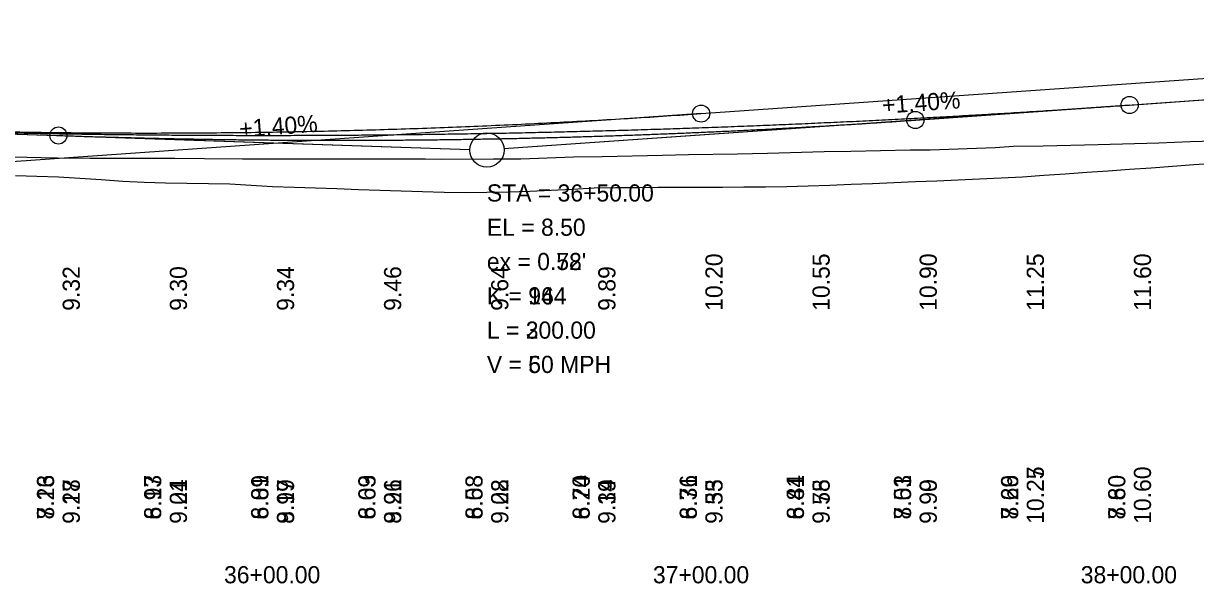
# Model space of a CAD drawing. Extents: x 3880794 to 3915434, y 287517 to 300173.
# Drawn here: x 3884080.1 to 3884353.7, y 296469.1 to 296599.8 of the extents above; entities that cross this region are included whole.
import ezdxf

# ---------------------------------------------------------------- set-up
doc = ezdxf.new("R2010")
doc.units = 0
for name, color, linetype in [('Level 1', 7, 'Continuous'), ('Level 2', 7, 'Continuous'), ('Level 30', 7, 'Continuous'), ('Level 31', 7, 'Continuous'), ('Level 32', 7, 'Continuous')]:
    doc.layers.add(name, color=color, linetype=linetype)

msp = doc.modelspace()

# ---------------------------------------------------------------- linework, layer by layer
at = {"layer": 'Level 1'}
for p, q in [((3884238.3, 296578.77), (3884538.3, 296599.8)), ((3884288.3, 296577.26), (3884538.3, 296594.76)), ((3884238.3, 296578.77), (3884042.29, 296565.04)), ((3884288.3, 296577.26), (3884192.29, 296570.54)), ((3884038.3, 296575.36), (3884088.3, 296573.66)), ((3884088.3, 296573.66), (3884184.3, 296570.39))]:
    msp.add_line(p, q, dxfattribs=at)
msp.add_lwpolyline([(3884067.5, 296568.95), (3884084.25, 296568.51), (3884088.11, 296568.41), (3884095.69, 296568.39), (3884105.7, 296568.38), (3884115.48, 296568.38), (3884122.37, 296568.31), (3884131.29, 296568.25), (3884136.3, 296568.22), (3884146.02, 296568.2), (3884152.71, 296568.19), (3884164.32, 296568.19), (3884173.94, 296568.18), (3884177.81, 296568.11), (3884189.81, 296568.18), (3884196.23, 296568.24), (3884208.54, 296568.65), (3884215.17, 296568.79), (3884229.31, 296569.1), (3884235.38, 296569.26), (3884246.77, 296569.4), (3884253.82, 296569.5), (3884267, 296569.89), (3884273.23, 296569.97), (3884287.11, 296570.3), (3884291.73, 296570.35), (3884306.93, 296570.86), (3884311.21, 296571.2), (3884318.13, 296571.24), (3884331, 296571.56), (3884345.09, 296571.95), (3884352.46, 296572.25), (3884366.62, 296572.68)], dxfattribs=at)
msp.add_circle((3884188.3, 296570.26), 4, dxfattribs=at)
for points in [[(3883838.3, 296594.09), (3883846.3, 296592.93), (3883854.3, 296591.81), (3883862.3, 296590.73), (3883870.3, 296589.67), (3883878.3, 296588.66), (3883886.3, 296587.67), (3883894.3, 296586.73), (3883902.3, 296585.81), (3883910.3, 296584.93), (3883918.3, 296584.09), (3883926.3, 296583.28), (3883934.3, 296582.51), (3883942.3, 296581.77), (3883950.3, 296581.06), (3883958.3, 296580.39), (3883966.3, 296579.76), (3883974.3, 296579.15), (3883982.3, 296578.59), (3883990.3, 296578.06), (3883998.3, 296577.56), (3884006.3, 296577.1), (3884014.3, 296576.67), (3884022.3, 296576.28), (3884030.3, 296575.92), (3884038.3, 296575.59), (3884046.3, 296575.31), (3884054.3, 296575.05), (3884062.3, 296574.83), (3884070.3, 296574.65), (3884078.3, 296574.5), (3884086.3, 296574.38), (3884094.3, 296574.3), (3884102.3, 296574.25), (3884110.3, 296574.24), (3884118.3, 296574.26), (3884126.3, 296574.32), (3884134.3, 296574.41), (3884142.3, 296574.54), (3884150.3, 296574.7), (3884158.3, 296574.9), (3884166.3, 296575.13), (3884174.3, 296575.4), (3884182.3, 296575.7), (3884190.3, 296576.03), (3884198.3, 296576.4), (3884206.3, 296576.81), (3884214.3, 296577.25), (3884222.3, 296577.72), (3884230.3, 296578.23), (3884238.3, 296578.77)], [(3884088.3, 296573.66), (3884092.3, 296573.53), (3884096.3, 296573.4), (3884100.3, 296573.29), (3884104.3, 296573.18), (3884108.3, 296573.08), (3884112.3, 296572.99), (3884116.3, 296572.91), (3884120.3, 296572.84), (3884124.3, 296572.77), (3884128.3, 296572.71), (3884132.3, 296572.66), (3884136.3, 296572.62), (3884140.3, 296572.59), (3884144.3, 296572.57), (3884148.3, 296572.55), (3884152.3, 296572.55), (3884156.3, 296572.55), (3884160.3, 296572.56), (3884164.3, 296572.57), (3884168.3, 296572.6), (3884172.3, 296572.64), (3884176.3, 296572.68), (3884180.3, 296572.73), (3884184.3, 296572.79), (3884188.3, 296572.86), (3884192.3, 296572.93), (3884196.3, 296573.02), (3884200.3, 296573.11), (3884204.3, 296573.21), (3884208.3, 296573.32), (3884212.3, 296573.44), (3884216.3, 296573.56), (3884220.3, 296573.7), (3884224.3, 296573.84), (3884228.3, 296573.99), (3884232.3, 296574.15), (3884236.3, 296574.32), (3884240.3, 296574.5), (3884244.3, 296574.68), (3884248.3, 296574.87), (3884252.3, 296575.07), (3884256.3, 296575.28), (3884260.3, 296575.5), (3884264.3, 296575.73), (3884268.3, 296575.96), (3884272.3, 296576.2), (3884276.3, 296576.45), (3884280.3, 296576.71), (3884284.3, 296576.98), (3884288.3, 296577.26)]]:
    msp.add_spline(points, degree=3, dxfattribs=at)
at = {"layer": 'Level 2'}
for p, q in [((3884338.3, 296580.76), (3884538.3, 296594.76)), ((3884338.3, 296580.76), (3884192.29, 296570.54)), ((3884038.3, 296575.36), (3884184.3, 296570.39))]:
    msp.add_line(p, q, dxfattribs=at)
msp.add_lwpolyline([(3884078.3, 296564.35), (3884083.3, 296564.19), (3884088.3, 296564.04), (3884093.3, 296563.74), (3884098.3, 296563.37), (3884103.3, 296562.98), (3884108.3, 296562.79), (3884113.3, 296562.61), (3884118.3, 296562.52), (3884123.3, 296562.46), (3884128.3, 296562.4), (3884133.3, 296562.1), (3884138.3, 296561.79), (3884143.3, 296561.58), (3884148.3, 296561.43), (3884153.3, 296561.27), (3884158.3, 296561.09), (3884163.3, 296560.91), (3884168.3, 296560.72), (3884173.3, 296560.56), (3884178.3, 296560.42), (3884183.3, 296560.37), (3884188.3, 296560.41), (3884193.3, 296560.53), (3884198.3, 296560.64), (3884203.3, 296560.88), (3884208.3, 296561.17), (3884213.3, 296561.45), (3884218.3, 296561.51), (3884223.3, 296561.54), (3884228.3, 296561.58), (3884233.3, 296561.58), (3884238.3, 296561.58), (3884243.3, 296561.6), (3884248.3, 296561.65), (3884253.3, 296561.69), (3884258.3, 296561.79), (3884263.3, 296561.95), (3884268.3, 296562.11), (3884273.3, 296562.29), (3884278.3, 296562.49), (3884283.3, 296562.69), (3884288.3, 296562.9), (3884293.3, 296563.12), (3884298.3, 296563.34), (3884303.3, 296563.58), (3884308.3, 296563.82), (3884313.3, 296564.05), (3884318.3, 296564.38), (3884323.3, 296564.74), (3884328.3, 296565.1), (3884333.3, 296565.44), (3884338.3, 296565.78), (3884343.3, 296566.13), (3884348.3, 296566.5), (3884353.3, 296566.87), (3884358.3, 296567.23)], dxfattribs=at)
for centre, radius in [((3884338.3, 296580.76), 2), ((3884188.3, 296570.26), 4)]:
    msp.add_circle(centre, radius, dxfattribs=at)
msp.add_spline([(3884038.3, 296575.36), (3884044.3, 296575.16), (3884050.3, 296574.97), (3884056.3, 296574.8), (3884062.3, 296574.64), (3884068.3, 296574.49), (3884074.3, 296574.36), (3884080.3, 296574.23), (3884086.3, 296574.12), (3884092.3, 296574.03), (3884098.3, 296573.94), (3884104.3, 296573.87), (3884110.3, 296573.81), (3884116.3, 296573.76), (3884122.3, 296573.72), (3884128.3, 296573.7), (3884134.3, 296573.69), (3884140.3, 296573.69), (3884146.3, 296573.71), (3884152.3, 296573.73), (3884158.3, 296573.77), (3884164.3, 296573.82), (3884170.3, 296573.89), (3884176.3, 296573.97), (3884182.3, 296574.06), (3884188.3, 296574.16), (3884194.3, 296574.27), (3884200.3, 296574.4), (3884206.3, 296574.54), (3884212.3, 296574.69), (3884218.3, 296574.85), (3884224.3, 296575.03), (3884230.3, 296575.22), (3884236.3, 296575.42), (3884242.3, 296575.63), (3884248.3, 296575.86), (3884254.3, 296576.1), (3884260.3, 296576.35), (3884266.3, 296576.62), (3884272.3, 296576.89), (3884278.3, 296577.18), (3884284.3, 296577.48), (3884290.3, 296577.8), (3884296.3, 296578.12), (3884302.3, 296578.46), (3884308.3, 296578.81), (3884314.3, 296579.18), (3884320.3, 296579.55), (3884326.3, 296579.94), (3884332.3, 296580.34), (3884338.3, 296580.76)], degree=3, dxfattribs=at)
at = {"layer": 'Level 31'}
for centre in [(3884238.3, 296578.77), (3884288.3, 296577.26), (3884088.3, 296573.66)]:
    msp.add_circle(centre, 2, dxfattribs=at)

# ---------------------------------------------------------------- texts
at = {"layer": 'Level 2'}
for s, rotation, p in [('+1.40%', 4.0042, (3884280.66, 296578.73)), ('10.27', 90, (3884318.3, 296483.07)), ('10.60', 90, (3884343.3, 296483.07)), ('9.27', 90, (3884093.3, 296483.07)), ('9.21', 90, (3884118.3, 296483.07)), ('9.19', 90, (3884143.3, 296483.07)), ('9.21', 90, (3884168.3, 296483.07)), ('9.28', 90, (3884193.3, 296483.07)), ('9.39', 90, (3884218.3, 296483.07)), ('9.55', 90, (3884243.3, 296483.07)), ('9.75', 90, (3884268.3, 296483.07)), ('9.99', 90, (3884293.3, 296483.07))]:
    msp.add_text(s, height=4, rotation=rotation, dxfattribs=at).set_placement(p)
for s, p in [('STA = 36+50.00', (3884188.3, 296558.26)), ('EL = 8.50', (3884188.3, 296550.26)), ("ex = 0.78'", (3884188.3, 296542.26)), ('K = 144', (3884188.3, 296534.26)), ('L = 300.00', (3884188.3, 296526.26)), ('V = 60 MPH', (3884188.3, 296518.26)), ('36+00.00', (3884126.96, 296469.2)), ('37+00.00', (3884227.05, 296469.2)), ('38+00.00', (3884326.9, 296469.2))]:
    msp.add_text(s, height=4, dxfattribs=at).set_placement(p)
at = {"layer": 'Level 30'}
for s, p in [('8.13', (3884087.3, 296484.08)), ('8.13', (3884112.3, 296484.08)), ('8.09', (3884137.3, 296484.08)), ('8.09', (3884162.3, 296484.08)), ('8.08', (3884187.3, 296484.08)), ('8.20', (3884212.3, 296484.08)), ('8.31', (3884237.3, 296484.08)), ('8.41', (3884262.3, 296484.08)), ('8.51', (3884287.3, 296484.08)), ('8.69', (3884312.3, 296484.08)), ('8.80', (3884337.3, 296484.08))]:
    msp.add_text(s, height=4, rotation=90, dxfattribs=at).set_placement(p)
for s, p in [('36+00.00', (3884126.96, 296469.2)), ('37+00.00', (3884227.05, 296469.2)), ('38+00.00', (3884326.9, 296469.2))]:
    msp.add_text(s, height=4, dxfattribs=at).set_placement(p)
at = {"layer": 'Level 31'}
for s, rotation, p in [('+1.40%', 4.0042, (3884280.66, 296578.73)), ('+1.40%', 4.0086, (3884130.66, 296573.23)), ('10.20', 90, (3884243.3, 296532.76)), ('10.55', 90, (3884268.3, 296532.76)), ('10.90', 90, (3884293.3, 296532.76)), ('11.25', 90, (3884318.3, 296532.76)), ('11.60', 90, (3884343.3, 296532.76)), ('9.32', 90, (3884093.3, 296532.76)), ('9.30', 90, (3884118.3, 296532.76)), ('9.34', 90, (3884143.3, 296532.76)), ('9.46', 90, (3884168.3, 296532.76)), ('9.64', 90, (3884193.3, 296532.76)), ('9.89', 90, (3884218.3, 296532.76)), ('10.25', 90, (3884318.3, 296483.07)), ('10.60', 90, (3884343.3, 296483.07)), ('9.18', 90, (3884093.3, 296483.07)), ('9.04', 90, (3884118.3, 296483.07)), ('8.97', 90, (3884143.3, 296483.07)), ('8.96', 90, (3884168.3, 296483.07)), ('9.02', 90, (3884193.3, 296483.07)), ('9.14', 90, (3884218.3, 296483.07)), ('9.33', 90, (3884243.3, 296483.07)), ('9.58', 90, (3884268.3, 296483.07)), ('9.90', 90, (3884293.3, 296483.07))]:
    msp.add_text(s, height=4, rotation=rotation, dxfattribs=at).set_placement(p)
for s, p in [('STA = 36+50.00', (3884188.3, 296558.26)), ('EL = 8.50', (3884188.3, 296550.26)), ("ex = 0.52'", (3884188.3, 296542.26)), ('K = 96', (3884188.3, 296534.26)), ('L = 200.00', (3884188.3, 296526.26)), ('V = 50 MPH', (3884188.3, 296518.26))]:
    msp.add_text(s, height=4, dxfattribs=at).set_placement(p)
at = {"layer": 'Level 32'}
for s, p in [('7.26', (3884087.3, 296484.08)), ('6.97', (3884112.3, 296484.08)), ('6.81', (3884137.3, 296484.08)), ('6.63', (3884162.3, 296484.08)), ('6.53', (3884187.3, 296484.08)), ('6.74', (3884212.3, 296484.08)), ('6.76', (3884237.3, 296484.08)), ('6.84', (3884262.3, 296484.08)), ('7.03', (3884287.3, 296484.08)), ('7.26', (3884312.3, 296484.08)), ('7.60', (3884337.3, 296484.08))]:
    msp.add_text(s, height=4, rotation=90, dxfattribs=at).set_placement(p)

doc.saveas('drawing.dxf')
